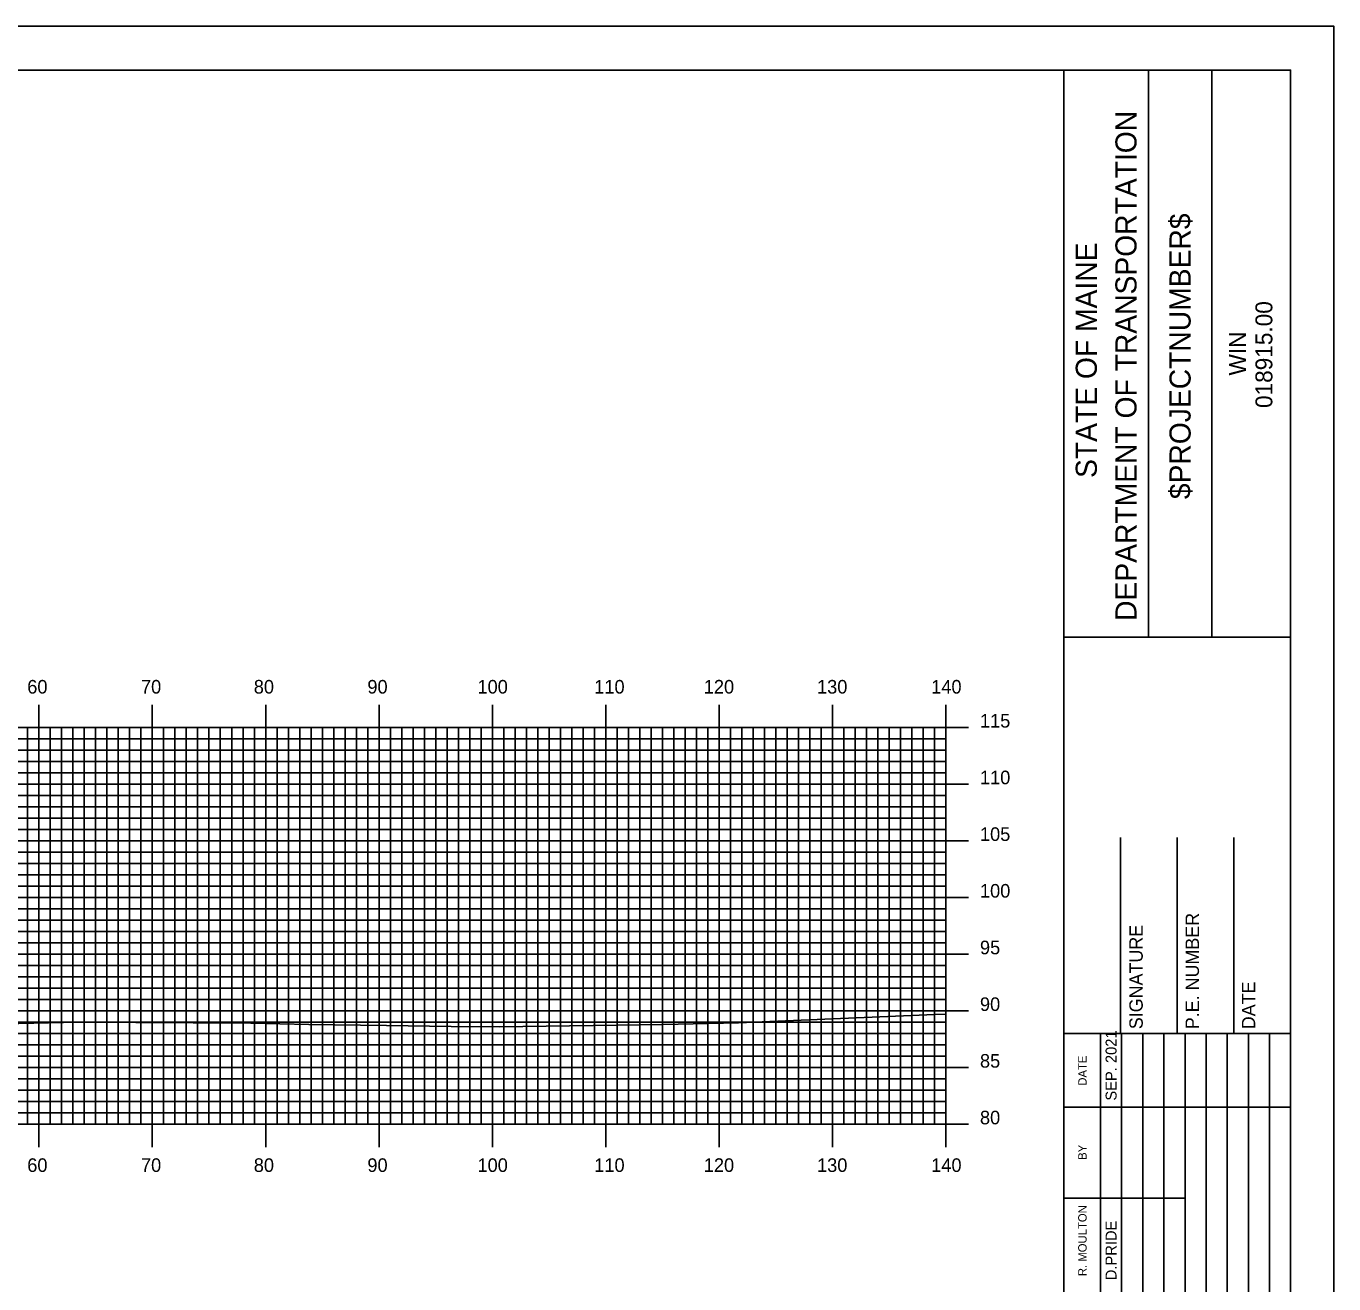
# Model space of a CAD drawing. Extents: x 1761397 to 1761741, y 442591 to 442811.
# Drawn here: x 1761622.1 to 1761737.5, y 442699.6 to 442810.5 of the extents above; entities that cross this region are included whole.
import ezdxf

# ---------------------------------------------------------------- set-up
doc = ezdxf.new("R2010")
doc.units = 0
for name, color, linetype in [('BORDER', 7, 'Continuous'), ('H_V ANNOTATION', 7, 'Continuous'), ('MAJOR', 7, 'Continuous'), ('MINOR', 7, 'Continuous'), ('PLOT BOUNDARY', 7, 'Continuous'), ('S_Roadway_Centerline', 7, 'Continuous')]:
    doc.layers.add(name, color=color, linetype=linetype)

msp = doc.modelspace()

# ---------------------------------------------------------------- linework, layer by layer
at = {"layer": 'BORDER'}
for p, q in [((1761713.64, 442596.67), (1761713.64, 442806.67)), ((1761721.1, 442756.66), (1761721.1, 442806.66)), ((1761726.69, 442756.66), (1761726.69, 442806.66)), ((1761713.64, 442756.65), (1761733.64, 442756.65)), ((1761718.64, 442721.67), (1761718.64, 442738.97)), ((1761723.64, 442721.67), (1761723.64, 442738.97)), ((1761728.64, 442721.67), (1761728.64, 442738.97)), ((1761713.64, 442721.67), (1761733.64, 442721.67))]:
    msp.add_line(p, q, dxfattribs=at)
msp.add_lwpolyline([(1761413.64, 442596.67), (1761733.64, 442596.67), (1761733.64, 442806.67), (1761413.64, 442806.67)], close=True, dxfattribs=at)
for points in [[(1761716.87, 442715.17), (1761716.87, 442721.67)], [(1761718.73, 442686.68), (1761718.73, 442721.67)], [(1761720.6, 442721.67), (1761720.6, 442686.68)], [(1761722.46, 442686.68), (1761722.46, 442721.67)], [(1761724.33, 442686.68), (1761724.33, 442721.67)], [(1761726.19, 442686.68), (1761726.19, 442721.67)], [(1761728.05, 442686.68), (1761728.05, 442721.67)], [(1761729.92, 442686.68), (1761729.92, 442721.67)], [(1761731.78, 442686.68), (1761731.78, 442721.67)], [(1761716.87, 442686.68), (1761716.87, 442720.26)], [(1761713.64, 442715.17), (1761733.64, 442715.17)], [(1761713.64, 442707.17), (1761716.87, 442707.17)], [(1761716.87, 442707.17), (1761724.32, 442707.17)]]:
    msp.add_lwpolyline(points, dxfattribs=at)
at = {"layer": 'MAJOR'}
for p, q in [((1761623.24, 442750.67), (1761623.24, 442748.67)), ((1761633.24, 442750.67), (1761633.24, 442748.67)), ((1761643.24, 442750.67), (1761643.24, 442748.67)), ((1761653.24, 442750.67), (1761653.24, 442748.67)), ((1761663.24, 442750.67), (1761663.24, 442748.67)), ((1761673.24, 442750.67), (1761673.24, 442748.67)), ((1761683.24, 442750.67), (1761683.24, 442748.67)), ((1761693.24, 442750.67), (1761693.24, 442748.67)), ((1761703.24, 442750.67), (1761703.24, 442748.67)), ((1761423.24, 442748.67), (1761703.24, 442748.67)), ((1761423.24, 442748.67), (1761703.24, 442748.67)), ((1761623.24, 442713.67), (1761623.24, 442748.67)), ((1761633.24, 442713.67), (1761633.24, 442748.67)), ((1761643.24, 442713.67), (1761643.24, 442748.67)), ((1761653.24, 442713.67), (1761653.24, 442748.67)), ((1761663.24, 442713.67), (1761663.24, 442748.67)), ((1761673.24, 442713.67), (1761673.24, 442748.67)), ((1761683.24, 442713.67), (1761683.24, 442748.67)), ((1761693.24, 442713.67), (1761693.24, 442748.67)), ((1761705.24, 442748.67), (1761701.24, 442748.67)), ((1761703.24, 442713.67), (1761703.24, 442748.67)), ((1761703.24, 442713.67), (1761703.24, 442748.67)), ((1761423.24, 442743.67), (1761703.24, 442743.67)), ((1761705.24, 442743.67), (1761701.24, 442743.67)), ((1761423.24, 442738.67), (1761703.24, 442738.67)), ((1761705.24, 442738.67), (1761701.24, 442738.67)), ((1761423.24, 442733.67), (1761703.24, 442733.67)), ((1761705.24, 442733.67), (1761701.24, 442733.67)), ((1761423.24, 442728.67), (1761703.24, 442728.67)), ((1761705.24, 442728.67), (1761701.24, 442728.67)), ((1761423.24, 442723.67), (1761703.24, 442723.67)), ((1761705.24, 442723.67), (1761701.24, 442723.67)), ((1761423.24, 442718.67), (1761703.24, 442718.67)), ((1761705.24, 442718.67), (1761701.24, 442718.67)), ((1761423.24, 442713.67), (1761703.24, 442713.67)), ((1761423.24, 442713.67), (1761703.24, 442713.67)), ((1761623.24, 442711.66), (1761623.24, 442713.67)), ((1761633.24, 442711.66), (1761633.24, 442713.67)), ((1761643.24, 442711.66), (1761643.24, 442713.67)), ((1761653.24, 442711.66), (1761653.24, 442713.67)), ((1761663.24, 442711.66), (1761663.24, 442713.67)), ((1761673.24, 442711.66), (1761673.24, 442713.67)), ((1761683.24, 442711.66), (1761683.24, 442713.67)), ((1761693.24, 442711.66), (1761693.24, 442713.67)), ((1761705.24, 442713.67), (1761701.24, 442713.67)), ((1761703.24, 442711.66), (1761703.24, 442713.67))]:
    msp.add_line(p, q, dxfattribs=at)
at = {"layer": 'MINOR'}
for p, q in [((1761622.24, 442713.67), (1761622.24, 442748.67)), ((1761624.24, 442713.67), (1761624.24, 442748.67)), ((1761625.24, 442713.67), (1761625.24, 442748.67)), ((1761626.24, 442713.67), (1761626.24, 442748.67)), ((1761627.24, 442713.67), (1761627.24, 442748.67)), ((1761628.24, 442713.67), (1761628.24, 442748.67)), ((1761629.24, 442713.67), (1761629.24, 442748.67)), ((1761630.24, 442713.67), (1761630.24, 442748.67)), ((1761631.24, 442713.67), (1761631.24, 442748.67)), ((1761632.24, 442713.67), (1761632.24, 442748.67)), ((1761634.24, 442713.67), (1761634.24, 442748.67)), ((1761635.24, 442713.67), (1761635.24, 442748.67)), ((1761636.24, 442713.67), (1761636.24, 442748.67)), ((1761637.24, 442713.67), (1761637.24, 442748.67)), ((1761638.24, 442713.67), (1761638.24, 442748.67)), ((1761639.24, 442713.67), (1761639.24, 442748.67)), ((1761640.24, 442713.67), (1761640.24, 442748.67)), ((1761641.24, 442713.67), (1761641.24, 442748.67)), ((1761642.24, 442713.67), (1761642.24, 442748.67)), ((1761644.24, 442713.67), (1761644.24, 442748.67)), ((1761645.24, 442713.67), (1761645.24, 442748.67)), ((1761646.24, 442713.67), (1761646.24, 442748.67)), ((1761647.24, 442713.67), (1761647.24, 442748.67)), ((1761648.24, 442713.67), (1761648.24, 442748.67)), ((1761649.24, 442713.67), (1761649.24, 442748.67)), ((1761650.24, 442713.67), (1761650.24, 442748.67)), ((1761651.24, 442713.67), (1761651.24, 442748.67)), ((1761652.24, 442713.67), (1761652.24, 442748.67)), ((1761654.24, 442713.67), (1761654.24, 442748.67)), ((1761655.24, 442713.67), (1761655.24, 442748.67)), ((1761656.24, 442713.67), (1761656.24, 442748.67)), ((1761657.24, 442713.67), (1761657.24, 442748.67)), ((1761658.24, 442713.67), (1761658.24, 442748.67)), ((1761659.24, 442713.67), (1761659.24, 442748.67)), ((1761660.24, 442713.67), (1761660.24, 442748.67)), ((1761661.24, 442713.67), (1761661.24, 442748.67)), ((1761662.24, 442713.67), (1761662.24, 442748.67)), ((1761664.24, 442713.67), (1761664.24, 442748.67)), ((1761665.24, 442713.67), (1761665.24, 442748.67)), ((1761666.24, 442713.67), (1761666.24, 442748.67)), ((1761667.24, 442713.67), (1761667.24, 442748.67)), ((1761668.24, 442713.67), (1761668.24, 442748.67)), ((1761669.24, 442713.67), (1761669.24, 442748.67)), ((1761670.24, 442713.67), (1761670.24, 442748.67)), ((1761671.24, 442713.67), (1761671.24, 442748.67)), ((1761672.24, 442713.67), (1761672.24, 442748.67)), ((1761674.24, 442713.67), (1761674.24, 442748.67)), ((1761675.24, 442713.67), (1761675.24, 442748.67)), ((1761676.24, 442713.67), (1761676.24, 442748.67)), ((1761677.24, 442713.67), (1761677.24, 442748.67)), ((1761678.24, 442713.67), (1761678.24, 442748.67)), ((1761679.24, 442713.67), (1761679.24, 442748.67)), ((1761680.24, 442713.67), (1761680.24, 442748.67)), ((1761681.24, 442713.67), (1761681.24, 442748.67)), ((1761682.24, 442713.67), (1761682.24, 442748.67)), ((1761684.24, 442713.67), (1761684.24, 442748.67)), ((1761685.24, 442713.67), (1761685.24, 442748.67)), ((1761686.24, 442713.67), (1761686.24, 442748.67)), ((1761687.24, 442713.67), (1761687.24, 442748.67)), ((1761688.24, 442713.67), (1761688.24, 442748.67)), ((1761689.24, 442713.67), (1761689.24, 442748.67)), ((1761690.24, 442713.67), (1761690.24, 442748.67)), ((1761691.24, 442713.67), (1761691.24, 442748.67)), ((1761692.24, 442713.67), (1761692.24, 442748.67)), ((1761694.24, 442713.67), (1761694.24, 442748.67)), ((1761695.24, 442713.67), (1761695.24, 442748.67)), ((1761696.24, 442713.67), (1761696.24, 442748.67)), ((1761697.24, 442713.67), (1761697.24, 442748.67)), ((1761698.24, 442713.67), (1761698.24, 442748.67)), ((1761699.24, 442713.67), (1761699.24, 442748.67)), ((1761700.24, 442713.67), (1761700.24, 442748.67)), ((1761701.24, 442713.67), (1761701.24, 442748.67)), ((1761702.24, 442713.67), (1761702.24, 442748.67)), ((1761423.24, 442747.67), (1761703.24, 442747.67)), ((1761703.24, 442747.67), (1761701.24, 442747.67)), ((1761423.24, 442746.67), (1761703.24, 442746.67)), ((1761703.24, 442746.67), (1761701.24, 442746.67)), ((1761423.24, 442745.67), (1761703.24, 442745.67)), ((1761703.24, 442745.67), (1761701.24, 442745.67)), ((1761423.24, 442744.67), (1761703.24, 442744.67)), ((1761703.24, 442744.67), (1761701.24, 442744.67)), ((1761423.24, 442742.67), (1761703.24, 442742.67)), ((1761423.24, 442741.67), (1761703.24, 442741.67)), ((1761703.24, 442742.67), (1761701.24, 442742.67)), ((1761703.24, 442741.67), (1761701.24, 442741.67)), ((1761423.24, 442740.67), (1761703.24, 442740.67)), ((1761703.24, 442740.67), (1761701.24, 442740.67)), ((1761423.24, 442739.67), (1761703.24, 442739.67)), ((1761703.24, 442739.67), (1761701.24, 442739.67)), ((1761423.24, 442737.67), (1761703.24, 442737.67)), ((1761703.24, 442737.67), (1761701.24, 442737.67)), ((1761423.24, 442736.67), (1761703.24, 442736.67)), ((1761703.24, 442736.67), (1761701.24, 442736.67)), ((1761423.24, 442735.67), (1761703.24, 442735.67)), ((1761423.24, 442734.67), (1761703.24, 442734.67)), ((1761703.24, 442735.67), (1761701.24, 442735.67)), ((1761703.24, 442734.67), (1761701.24, 442734.67)), ((1761423.24, 442732.67), (1761703.24, 442732.67)), ((1761703.24, 442732.67), (1761701.24, 442732.67)), ((1761423.24, 442731.67), (1761703.24, 442731.67)), ((1761703.24, 442731.67), (1761701.24, 442731.67)), ((1761423.24, 442730.67), (1761703.24, 442730.67)), ((1761703.24, 442730.67), (1761701.24, 442730.67)), ((1761423.24, 442729.67), (1761703.24, 442729.67)), ((1761703.24, 442729.67), (1761701.24, 442729.67)), ((1761423.24, 442727.67), (1761703.24, 442727.67)), ((1761423.24, 442726.67), (1761703.24, 442726.67)), ((1761703.24, 442727.67), (1761701.24, 442727.67)), ((1761703.24, 442726.67), (1761701.24, 442726.67)), ((1761423.24, 442725.67), (1761703.24, 442725.67)), ((1761703.24, 442725.67), (1761701.24, 442725.67)), ((1761423.24, 442724.67), (1761703.24, 442724.67)), ((1761703.24, 442724.67), (1761701.24, 442724.67)), ((1761423.24, 442722.67), (1761703.24, 442722.67)), ((1761703.24, 442722.67), (1761701.24, 442722.67)), ((1761423.24, 442721.67), (1761703.24, 442721.67)), ((1761703.24, 442721.67), (1761701.24, 442721.67)), ((1761423.24, 442720.67), (1761703.24, 442720.67)), ((1761423.24, 442719.67), (1761703.24, 442719.67)), ((1761703.24, 442720.67), (1761701.24, 442720.67)), ((1761703.24, 442719.67), (1761701.24, 442719.67)), ((1761423.24, 442717.67), (1761703.24, 442717.67)), ((1761703.24, 442717.67), (1761701.24, 442717.67)), ((1761423.24, 442716.67), (1761703.24, 442716.67)), ((1761703.24, 442716.67), (1761701.24, 442716.67)), ((1761423.24, 442715.67), (1761703.24, 442715.67)), ((1761703.24, 442715.67), (1761701.24, 442715.67)), ((1761423.24, 442714.67), (1761703.24, 442714.67)), ((1761703.24, 442714.67), (1761701.24, 442714.67))]:
    msp.add_line(p, q, dxfattribs=at)
at = {"layer": 'PLOT BOUNDARY'}
msp.add_lwpolyline([(1761397.45, 442590.55), (1761737.45, 442590.55), (1761737.45, 442810.55), (1761397.45, 442810.55)], close=True, dxfattribs=at)
at = {"layer": 'S_Roadway_Centerline'}
msp.add_lwpolyline([(1761620.18, 442722.54), (1761626.71, 442722.68), (1761641.94, 442722.58), (1761647.04, 442722.48), (1761653.89, 442722.39), (1761659.6, 442722.29), (1761663.86, 442722.28), (1761678.3, 442722.49), (1761684.93, 442722.63), (1761702.26, 442723.35), (1761703.24, 442723.39)], dxfattribs=at)

# ---------------------------------------------------------------- texts
at = {"layer": 'BORDER'}
for s, height, p in [('DEPARTMENT OF TRANSPORTATION', 1.8635, (1761720.05, 442758.08)), ('$PROJECTNUMBER$', 1.8635, (1761724.82, 442768.82)), ('STATE OF MAINE', 1.8635, (1761716.55, 442770.69)), ('018915.00', 1.491, (1761732.03, 442776.86)), ('WIN', 1.491, (1761729.71, 442779.73)), ('SIGNATURE', 1.181, (1761720.6, 442722.06)), ('P.E. NUMBER', 1.1811, (1761725.56, 442722.06)), ('DATE', 1.181, (1761730.52, 442722.06)), ('SEP. 2021', 0.969, (1761718.29, 442715.76)), ('DATE', 0.743, (1761715.65, 442717.08)), ('BY', 0.743, (1761715.65, 442710.54)), ('R. MOULTON', 0.745, (1761715.65, 442700.28)), ('D.PRIDE', 0.969, (1761718.29, 442699.92))]:
    msp.add_text(s, height=height, rotation=90, dxfattribs=at).set_placement(p)
at = {"layer": 'H_V ANNOTATION'}
for s, p in [('60', (1761622.21, 442751.67)), ('70', (1761632.24, 442751.67)), ('80', (1761642.19, 442751.67)), ('90', (1761652.21, 442751.67)), ('100', (1761661.92, 442751.67)), ('110', (1761672.22, 442751.67)), ('120', (1761681.88, 442751.67)), ('130', (1761691.87, 442751.67)), ('140', (1761701.94, 442751.67)), ('115', (1761706.24, 442748.67)), ('110', (1761706.24, 442743.67)), ('105', (1761706.24, 442738.67)), ('100', (1761706.24, 442733.67)), ('95', (1761706.24, 442728.67)), ('90', (1761706.24, 442723.67)), ('85', (1761706.24, 442718.67)), ('80', (1761706.24, 442713.67)), ('60', (1761622.21, 442709.47)), ('70', (1761632.24, 442709.47)), ('80', (1761642.19, 442709.47)), ('90', (1761652.21, 442709.47)), ('100', (1761661.92, 442709.47)), ('110', (1761672.22, 442709.47)), ('120', (1761681.88, 442709.47)), ('130', (1761691.87, 442709.47)), ('140', (1761701.94, 442709.47))]:
    msp.add_text(s, height=1.2, dxfattribs=at).set_placement(p)

doc.saveas('drawing.dxf')
